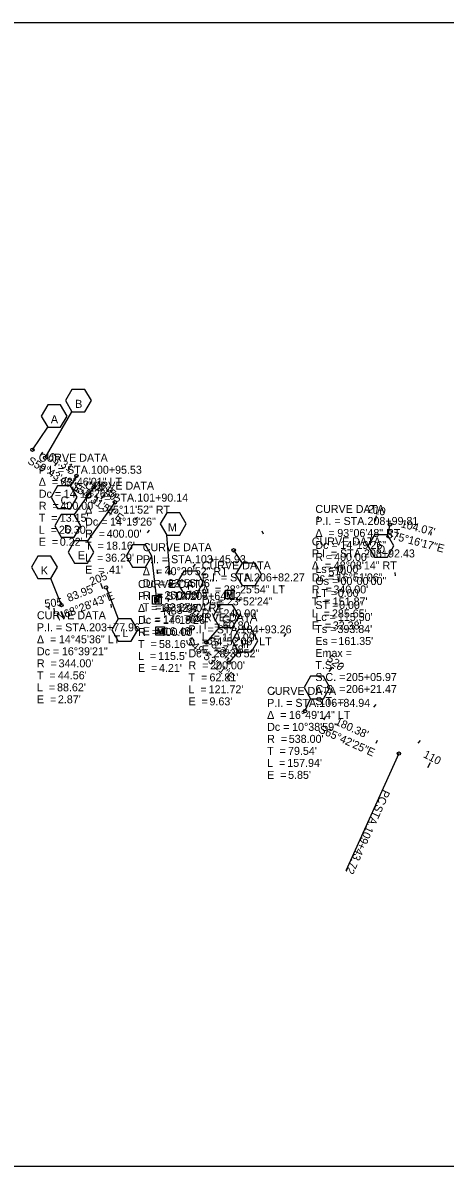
# Model space of a CAD drawing. Extents: x 1597353 to 1604853, y 283653 to 289007.
# Drawn here: x 1600756 to 1601495, y 285653 to 287653 of the extents above; entities that cross this region are included whole.
import ezdxf

# ---------------------------------------------------------------- set-up
doc = ezdxf.new("R2010")
doc.units = 0
for name, color, linetype in [('_CIVIL_CONSTRUCTION', 7, 'Continuous'), ('GE_X_Alignment_100_Cardinal_Points', 7, 'Continuous'), ('GE_X_Alignment_100_Curve_Data', 7, 'Continuous'), ('GE_X_Alignment_100_Distances', 7, 'Continuous'), ('GE_X_Alignment_100_Stations', 7, 'Continuous'), ('RW_P_Text', 7, 'Continuous'), ('SH_Border', 7, 'Continuous'), ('SH_Cut_Line', 7, 'Continuous'), ('SH_Data', 7, 'Continuous'), ('SH_Masking', 7, 'Continuous'), ('SH_Text', 7, 'Continuous')]:
    doc.layers.add(name, color=color, linetype=linetype)

msp = doc.modelspace()

# ---------------------------------------------------------------- linework, layer by layer
at = {"layer": '_CIVIL_CONSTRUCTION'}
msp.add_lwpolyline([(1599853.4, 287653.4), (1599853.4, 285653.4), (1600103.4, 285653.4), (1600353.4, 285653.4), (1600603.4, 285653.4), (1600853.4, 285653.4), (1601103.4, 285653.4), (1601353.4, 285653.4), (1601603.4, 285653.4), (1601853.4, 285653.4), (1602103.4, 285653.4), (1602353.4, 285653.4), (1602353.4, 287653.4), (1602103.4, 287653.4), (1601853.4, 287653.4), (1601603.4, 287653.4), (1601353.4, 287653.4), (1601103.4, 287653.4), (1600853.4, 287653.4), (1600603.4, 287653.4), (1600353.4, 287653.4), (1600103.4, 287653.4)], close=True, dxfattribs=at)
at = {"layer": 'GE_X_Alignment_100_Curve_Data'}
msp.add_line((1600990.8, 286639.2), (1600981.7, 286720.7), dxfattribs=at)
msp.add_lwpolyline([(1600981.7, 286720.7), (1600970.3, 286740.3), (1600947.7, 286740.3), (1600936.3, 286720.7), (1600947.7, 286701.1), (1600970.3, 286701.1)], close=True, dxfattribs=at)
msp.add_circle((1600990.8, 286639.2), 3, dxfattribs=at)
at = {"layer": 'GE_X_Alignment_100_Stations'}
for p, q in [((1600811.9, 286878.4), (1600815.3, 286883.3)), ((1600893.1, 286820.1), (1600898.9, 286828.1)), ((1600973.8, 286761), (1600977.4, 286765.9)), ((1601054.1, 286701.4), (1601057.7, 286706.2)), ((1601308.8, 286674.7), (1601307.6, 286684.6)), ((1601408.1, 286685.8), (1601407.5, 286691.7)), ((1601209.4, 286663.6), (1601208.7, 286669.6)), ((1601010.6, 286641.4), (1601009.9, 286647.4)), ((1601110, 286652.5), (1601109.3, 286658.5)), ((1601133.8, 286641.1), (1601137.5, 286645.9)), ((1600811.8, 286619.6), (1600810.7, 286629.5)), ((1600911.2, 286630.5), (1600910.6, 286636.4)), ((1601213.1, 286580.1), (1601216.8, 286584.9)), ((1601291.9, 286518.5), (1601298.1, 286526.4)), ((1601370.2, 286456.3), (1601373.9, 286461)), ((1601447.9, 286393.4), (1601451.7, 286398.1))]:
    msp.add_line(p, q, dxfattribs=at)
at = {"layer": 'RW_P_Text'}
for p, q in [((1600990.2, 286644.2), (1600990.2, 286644.2)), ((1601117.7, 286653.4), (1601117.7, 286653.4)), ((1600996.2, 286589.5), (1600996.2, 286589.5))]:
    msp.add_line(p, q, dxfattribs=at)
for points in [[(1601110.2, 286660.9), (1601125.2, 286660.9), (1601125.2, 286645.9), (1601110.2, 286645.9), (1601110.2, 286660.9)], [(1600982.7, 286651.7), (1600997.7, 286651.7), (1600997.7, 286636.7), (1600982.7, 286636.7), (1600982.7, 286651.7)], [(1600986.5, 286639.2), (1600986.5, 286649.2), (1600990.2, 286639.2), (1600993.9, 286649.2), (1600993.9, 286639.2)], [(1601114, 286648.4), (1601114, 286658.4), (1601117.7, 286648.4), (1601121.4, 286658.4), (1601121.4, 286648.4)], [(1600988.7, 286597), (1601003.7, 286597), (1601003.7, 286582), (1600988.7, 286582), (1600988.7, 286597)], [(1600992.5, 286584.5), (1600992.5, 286594.5), (1600996.2, 286584.5), (1600999.9, 286594.5), (1600999.9, 286584.5)]]:
    msp.add_lwpolyline(points, dxfattribs=at)
at = {"layer": 'SH_Border'}
for p, q in [((1600794.8, 286892.6), (1600841.7, 286972.9)), ((1600772.5, 286906.6), (1600799.2, 286946)), ((1600849.5, 286860.7), (1600839.3, 286843.2)), ((1600879.9, 286841), (1600845.8, 286793.1)), ((1600916.9, 286814.6), (1600868.9, 286747.2)), ((1601398.3, 286775.7), (1601393.7, 286758)), ((1601013.3, 286691.9), (1601007.7, 286757)), ((1601124.7, 286730.7), (1601139.5, 286708.3)), ((1600823.2, 286634.8), (1600804.9, 286681.3)), ((1600901.3, 286665.6), (1600922.8, 286611)), ((1601014.4, 286671.6), (1601026, 286674.5)), ((1601076.9, 286569.3), (1601100, 286595.8)), ((1601117, 286534.3), (1601133.2, 286552.9)), ((1601249.5, 286449.3), (1601259.2, 286470.9)), ((1601413.9, 286375.1), (1601321.3, 286170))]:
    msp.add_line(p, q, dxfattribs=at)
for points in [[(1600875.7, 286992.5), (1600864.3, 287012.1), (1600841.7, 287012.1), (1600830.3, 286992.5), (1600841.7, 286972.9), (1600864.3, 286972.9)], [(1600833.2, 286965.6), (1600821.8, 286985.3), (1600799.2, 286985.3), (1600787.8, 286965.6), (1600799.2, 286946), (1600821.8, 286946)], [(1600850.6, 286823.5), (1600839.3, 286843.2), (1600816.6, 286843.2), (1600805.3, 286823.5), (1600816.6, 286803.9), (1600839.3, 286803.9)], [(1600857.1, 286773.4), (1600845.8, 286793.1), (1600823.1, 286793.1), (1600811.8, 286773.4), (1600823.1, 286753.8), (1600845.8, 286753.8)], [(1601041.7, 286776.7), (1601030.4, 286796.3), (1601007.7, 286796.3), (1600996.3, 286776.7), (1601007.7, 286757), (1601030.4, 286757)], [(1600880.2, 286727.6), (1600868.9, 286747.2), (1600846.2, 286747.2), (1600834.9, 286727.6), (1600846.2, 286707.9), (1600868.9, 286707.9)], [(1601405, 286738.4), (1601393.7, 286758), (1601371, 286758), (1601359.7, 286738.4), (1601371, 286718.8), (1601393.7, 286718.8)], [(1600816.2, 286701), (1600804.9, 286720.6), (1600782.2, 286720.6), (1600770.9, 286701), (1600782.2, 286681.3), (1600804.9, 286681.3)], [(1601173.5, 286688.6), (1601162.1, 286708.3), (1601139.5, 286708.3), (1601128.1, 286688.6), (1601139.5, 286669), (1601162.1, 286669)], [(1601071.3, 286674.5), (1601060, 286694.1), (1601037.3, 286694.1), (1601026, 286674.5), (1601037.3, 286654.8), (1601060, 286654.8)], [(1601134.1, 286615.4), (1601122.7, 286635.1), (1601100, 286635.1), (1601088.7, 286615.4), (1601100, 286595.8), (1601122.7, 286595.8)], [(1600956.8, 286591.4), (1600945.5, 286611), (1600922.8, 286611), (1600911.5, 286591.4), (1600922.8, 286571.8), (1600945.5, 286571.8)], [(1601167.2, 286572.5), (1601155.9, 286592.1), (1601133.2, 286592.1), (1601121.9, 286572.5), (1601133.2, 286552.9), (1601155.9, 286552.9)], [(1601293.2, 286490.5), (1601281.9, 286510.2), (1601259.2, 286510.2), (1601247.9, 286490.5), (1601259.2, 286470.9), (1601281.9, 286470.9)]]:
    msp.add_lwpolyline(points, close=True, dxfattribs=at)
for centre in [(1600772.5, 286906.6), (1600794.8, 286892.6), (1600849.5, 286860.7), (1600879.9, 286841), (1600916.9, 286814.6), (1601398.3, 286775.7), (1601124.7, 286730.7), (1601013.3, 286691.9), (1600901.3, 286665.6), (1601014.4, 286671.6), (1600823.2, 286634.8), (1601076.9, 286569.3), (1601117, 286534.3), (1601249.5, 286449.3), (1601413.9, 286375.1)]:
    msp.add_circle(centre, 3, dxfattribs=at)
at = {"layer": 'SH_Text'}
for p, q in [((1600787.4, 286897), (1600790.5, 286902.1)), ((1600873.2, 286845.7), (1600876.5, 286850.6)), ((1600951.9, 286784.4), (1600956.3, 286788.6)), ((1601273.1, 286784.7), (1601272.5, 286790.6)), ((1601372.7, 286781.4), (1601374.5, 286791.2)), ((1601176.9, 286758.9), (1601174.5, 286764.4)), ((1601469.7, 286756.9), (1601471.2, 286762.8)), ((1601005.3, 286700.6), (1601010.9, 286702.7)), ((1601089.1, 286711.3), (1601086.7, 286716.8)), ((1600992, 286689.5), (1600991.2, 286695.5)), ((1600895.8, 286663.4), (1600892.1, 286672.7)), ((1600802.5, 286627.4), (1600800.6, 286633.1)), ((1601042.5, 286608.3), (1601050.8, 286613.9)), ((1601113, 286537.9), (1601116.9, 286542.4)), ((1601193.4, 286478.7), (1601196.5, 286483.8)), ((1601282.9, 286434.2), (1601285.4, 286439.7)), ((1601374, 286393.1), (1601376.5, 286398.5)), ((1601464.5, 286350.5), (1601469.1, 286359.4))]:
    msp.add_line(p, q, dxfattribs=at)

# ---------------------------------------------------------------- texts
at = {"layer": 'GE_X_Alignment_100_Cardinal_Points'}
msp.add_text('N83°37\'47"E', height=14, rotation=6.3702, dxfattribs=at).set_placement((1601001.7, 286616.3))
at = {"layer": 'GE_X_Alignment_100_Curve_Data'}
msp.add_text('P', height=14, dxfattribs=at).set_placement((1600954, 286708.1))
at = {"layer": 'GE_X_Alignment_100_Distances'}
msp.add_text("127.73'", height=14, rotation=6.3702, dxfattribs=at).set_placement((1601022.2, 286642.9))
at = {"layer": 'GE_X_Alignment_100_Stations'}
for s, rotation, p in [('515', 324.0747, (1600887.4, 286839.6)), ('510', 6.3702, (1601291.1, 286685.3)), ('505', 6.2535, (1600794.5, 286630.2)), ('520', 321.7414, (1601286.8, 286538.5))]:
    msp.add_text(s, height=14, rotation=rotation, dxfattribs=at).set_placement(p)
at = {"layer": 'SH_Border'}
for s, p in [('B', (1600847.3, 286979.9)), ('A', (1600804.8, 286953)), ('C', (1600821.8, 286810.9)), ('D', (1600827.9, 286760.8)), ('M', (1601009.7, 286764.1)), ('O', (1601375.4, 286725.8)), ('E', (1600852, 286715)), ('K', (1600787.3, 286688.4)), ('N', (1601143.8, 286676)), ('F', (1601043.2, 286661.9)), ('G', (1601104.5, 286602.8)), ('L', (1600930, 286578.8)), ('H', (1601137.7, 286559.9)), ('I', (1601267.8, 286477.9))]:
    msp.add_text(s, height=14, dxfattribs=at).set_placement(p)
for s, p in [('PC', (1601386.2, 286313.1)), (' STA. ', (1601376.7, 286292.2)), ('109+43.72', (1601357.3, 286249.2))]:
    msp.add_text(s, height=14, rotation=245.7068, dxfattribs=at).set_placement(p)
at = {"layer": 'SH_Cut_Line'}
for s, rotation, p in [('S59°43\'45"E', 329.7293, (1600762.8, 286883.4)), ('S54°31\'54"E', 324.5316, (1600840, 286840)), ('S75°16\'17"E', 345.2715, (1601389.6, 286753.2)), ('N68°28\'43"E', 21.5214, (1600818.2, 286607)), ('S48°53\'11"E', 318.8864, (1601040, 286569.7)), ('S65°42\'25"E', 335.7068, (1601272, 286412.8))]:
    msp.add_text(s, height=14, rotation=rotation, dxfattribs=at).set_placement(p)
at = {"layer": 'SH_Data'}
for s, p in [('CURVE DATA', (1600783.7, 286885.6)), ('P.I. = STA. ', (1600783.7, 286864.6)), ('100+95.53', (1600875, 286864.6)), ('Δ  = ', (1600783.7, 286843.6)), ('03°46\'01" LT', (1600822, 286843.6)), ('CURVE DATA', (1600864.7, 286836.8)), ('Dc = ', (1600783.7, 286822.6)), ('14°19\'26"', (1600827.4, 286822.6)), ('P.I. = STA. ', (1600864.7, 286815.8)), ('101+90.14', (1600956, 286815.8)), ('R  = ', (1600783.7, 286801.6)), ("400.00'", (1600821.6, 286801.6)), ('Δ  = ', (1600864.7, 286794.8)), ('05°11\'52" RT', (1600903.1, 286794.8)), ('CURVE DATA', (1601267.7, 286796)), ('T  = ', (1600783.7, 286780.6)), ("13.15'", (1600820.4, 286780.6)), ('Dc = ', (1600864.7, 286773.8)), ('14°19\'26"', (1600908.4, 286773.8)), ('P.I. = STA. ', (1601267.7, 286775)), ('208+99.81', (1601359, 286775)), ('L  = ', (1600783.7, 286759.6)), ("26.30'", (1600818.9, 286759.6)), ('R  = ', (1600864.7, 286752.8)), ("400.00'", (1600902.6, 286752.8)), ('Δ  = ', (1601267.7, 286754)), ('93°06\'48" RT', (1601306.1, 286754)), ('E  = ', (1600783.7, 286738.6)), ("0.22'", (1600820.4, 286738.6)), ('T  = ', (1600864.7, 286731.8)), ("18.16'", (1600901.4, 286731.8)), ('CURVE DATA', (1600965.7, 286729.1)), ('CURVE DATA', (1601261.5, 286739.2)), ('Dc = ', (1601267.7, 286733)), ('14°19\'26"', (1601311.4, 286733)), ('L  = ', (1600864.7, 286710.8)), ("36.29'", (1600899.9, 286710.8)), ('P.I. = STA. ', (1600965.7, 286708.1)), ('103+45.93', (1601057, 286708.1)), ('P.I. = STA. ', (1601261.5, 286718.2)), ('R = ', (1601267.7, 286712)), ("400.00'", (1601300.6, 286712)), ('208+92.43', (1601352.8, 286718.2)), ('E  = ', (1600864.7, 286689.8)), (".41'", (1600901.4, 286689.8)), ('Δ  = ', (1600965.7, 286687.1)), ('40°30\'52" RT', (1601004, 286687.1)), ('CURVE DATA', (1601069, 286697.3)), ('Δ  = ', (1601261.5, 286697.2)), ('Ls = ', (1601267.7, 286691)), ('48°08\'14" RT', (1601299.9, 286697.2)), ("0.00'", (1601306.5, 286691)), ('Dc = ', (1600965.7, 286666.1)), ('22°55\'06"', (1601009.4, 286666.1)), ('P.I. = STA. ', (1601069, 286676.3)), ('206+82.27', (1601160.3, 286676.3)), ('Dc = ', (1601261.5, 286676.2)), ('Θs = ', (1601267.7, 286670)), ('16°51\'06"', (1601305.2, 286676.2)), ('00°00\'00"', (1601311.7, 286670)), ('CURVE DATA', (1600957.3, 286664.8)), ('Δ  = ', (1601069, 286655.3)), ('28°25\'54" LT', (1601107.4, 286655.3)), ('R  = ', (1601261.5, 286655.2)), ('LT = ', (1601267.7, 286649)), ("340.00'", (1601299.4, 286655.2)), ("0.00'", (1601307, 286649)), ('P.I. = STA. ', (1600957.3, 286643.8)), ('R  = ', (1600965.7, 286645.1)), ("250.00'", (1601003.6, 286645.1)), ('205+64.12', (1601048.7, 286643.8)), ('Dc = ', (1601069, 286634.3)), ('23°52\'24"', (1601112.7, 286634.3)), ('T  = ', (1601261.5, 286634.2)), ('ST = ', (1601267.7, 286628)), ("151.87'", (1601298.2, 286634.2)), ("0.00'", (1601309.2, 286628)), ('CURVE DATA', (1600780.4, 286610)), ('Δ  = ', (1600957.3, 286622.8)), ('T  = ', (1600965.7, 286624.1)), ('16°32\'40" RT', (1600995.7, 286622.8)), ("92.27'", (1601002.3, 286624.1)), ('CURVE DATA', (1601045.7, 286606.4)), ('R  = ', (1601069, 286613.3)), ("240.00'", (1601106.9, 286613.3)), ('L  = ', (1601261.5, 286613.2)), ('Lc = ', (1601267.7, 286607)), ("285.65'", (1601296.7, 286613.2)), ("115.50'", (1601307.1, 286607)), ('P.I. = STA. ', (1600780.4, 286589)), ('203+77.96', (1600871.7, 286589)), ('Dc = ', (1600957.3, 286601.8)), ('L  = ', (1600965.7, 286603.1)), ("176.78'", (1601000.9, 286603.1)), ('14°19\'26"', (1601001, 286601.8)), ('T  = ', (1601069, 286592.3)), ("60.80'", (1601105.7, 286592.3)), ('E  = ', (1601261.5, 286592.2)), ('Ts = ', (1601267.7, 286586)), ("32.38'", (1601298.2, 286592.2)), ("393.84'", (1601306.4, 286586)), ('Δ  = ', (1600780.4, 286568)), ('14°45\'36" LT', (1600818.8, 286568)), ('R  = ', (1600957.3, 286580.8)), ('E  = ', (1600965.7, 286582.1)), ("400.00'", (1600995.2, 286580.8)), ("16.48'", (1601002.4, 286582.1)), ('P.I. = STA. ', (1601045.7, 286585.4)), ('L  = ', (1601069, 286571.3)), ("119.09'", (1601104.2, 286571.3)), ('104+93.26', (1601137, 286585.4)), ('Dc = ', (1600780.4, 286547)), ('16°39\'21"', (1600824.1, 286547)), ('T  = ', (1600957.3, 286559.8)), ("58.16'", (1600994, 286559.8)), ('Δ  = ', (1601045.7, 286564.4)), ('E  = ', (1601069, 286550.3)), ('34°52\'09" LT', (1601084.1, 286564.4)), ("7.58'", (1601105.7, 286550.3)), ('Es = ', (1601267.7, 286565)), ("161.35'", (1601308, 286565)), ("344.00'", (1600818.3, 286526)), ('L  = ', (1600957.3, 286538.8)), ("115.5'", (1600992.5, 286538.8)), ('Dc = ', (1601045.7, 286543.4)), ('28°38\'52"', (1601089.4, 286543.4)), ('Emax = ', (1601267.7, 286544)), ('R  = ', (1600780.4, 286526)), ('E  = ', (1600957.3, 286517.8)), ("4.21'", (1600994, 286517.8)), ('R  = ', (1601045.7, 286522.4)), ("200.00'", (1601083.6, 286522.4)), ('T.S. = ', (1601267.7, 286523)), ('T  = ', (1600780.4, 286505)), ("44.56'", (1600817.1, 286505)), ('T  = ', (1601045.7, 286501.4)), ("62.81'", (1601082.4, 286501.4)), ('S.C. = ', (1601267.7, 286502)), ('205+05.97', (1601321.3, 286502)), ('L  = ', (1600780.4, 286484)), ("88.62'", (1600815.6, 286484)), ('L  = ', (1601045.7, 286480.4)), ("121.72'", (1601080.9, 286480.4)), ('CURVE DATA', (1601183.3, 286477.8)), ('C.S. = ', (1601267.7, 286481)), ('206+21.47', (1601321.3, 286481)), ('E  = ', (1600780.4, 286463)), ("2.87'", (1600817.1, 286463)), ('E  = ', (1601045.7, 286459.4)), ("9.63'", (1601082.4, 286459.4)), ('P.I. = STA. ', (1601183.3, 286456.8)), ('S.T. = ', (1601267.7, 286460)), ('106+84.94', (1601274.6, 286456.8)), ('Δ  = ', (1601183.3, 286435.8)), ('16°49\'14" LT', (1601221.6, 286435.8)), ('Dc = ', (1601183.3, 286414.8)), ('10°38\'59"', (1601227, 286414.8)), ('R  = ', (1601183.3, 286393.8)), ("538.00'", (1601221.2, 286393.8)), ('T  = ', (1601183.3, 286372.8)), ("79.54'", (1601219.9, 286372.8)), ('L  = ', (1601183.3, 286351.8)), ("157.94'", (1601218.5, 286351.8)), ('E  = ', (1601183.3, 286330.8)), ("5.85'", (1601220, 286330.8))]:
    msp.add_text(s, height=14, dxfattribs=at).set_placement(p)
at = {"layer": 'SH_Masking'}
for s, rotation, p in [("63.31'", 329.7293, (1600798.2, 286890.8)), ("45.40'", 324.5316, (1600875.9, 286844.1)), ("104.07'", 345.2715, (1601416.4, 286771.2)), ("83.95'", 21.5214, (1600836.3, 286640.2)), ("53.24'", 318.8864, (1601076.2, 286570.3)), ("180.38'", 335.7068, (1601301.3, 286426.1))]:
    msp.add_text(s, height=14, rotation=rotation, dxfattribs=at).set_placement(p)
at = {"layer": 'SH_Text'}
for s, rotation, p in [('210', 349.6896, (1601358.5, 286796.7)), ('205', 21.5214, (1600875.8, 286668.9)), ('105', 303.9428, (1601043.7, 286629)), ('110', 332.4824, (1601455.4, 286369.3))]:
    msp.add_text(s, height=14, rotation=rotation, dxfattribs=at).set_placement(p)

doc.saveas('drawing.dxf')
